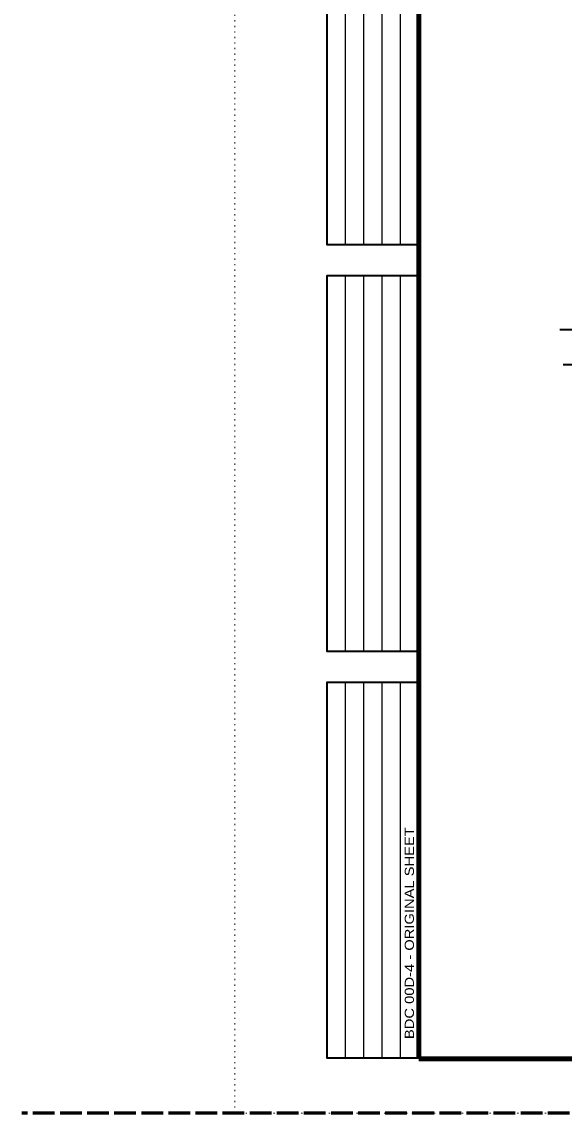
# Model space of a CAD drawing. Extents: x 312583 to 312854, y 144419 to 144597.
# Drawn here: x 312583.5 to 312628.6, y 144418.6 to 144509.2 of the extents above; entities that cross this region are included whole.
import ezdxf

# ---------------------------------------------------------------- set-up
doc = ezdxf.new("R2010")
doc.units = 0
doc.header["$LTSCALE"] = 0.3
doc.linetypes.add('DOTTED', pattern=[1.5, 0.3, -1.2])
doc.linetypes.add('LONG_DASHED', pattern=[7.5, 6, -1.5])
for name, color, linetype, lineweight in [('1', 7, 'Continuous', 40), ('2', 7, 'Continuous', 13), ('63', 7, 'DOTTED', 13)]:
    doc.layers.add(name, color=color, linetype=linetype, lineweight=lineweight)

msp = doc.modelspace()

# ---------------------------------------------------------------- linework, layer by layer
at = {"layer": '1', "linetype": 'DOTTED', "lineweight": 13}
msp.add_line((312601.2, 144418.5846), (312601.2, 144596.7846), dxfattribs=at)
at = {"layer": '1', "lineweight": 25}
for p, q in [((312610.4087, 144490.6573), (312610.4087, 144521.8756)), ((312611.9315, 144490.6573), (312611.9315, 144521.8756)), ((312613.4543, 144490.6573), (312613.4543, 144521.8756)), ((312614.9772, 144490.6573), (312614.9772, 144521.8756)), ((312610.4087, 144456.901), (312610.4087, 144488.1192)), ((312611.9315, 144456.901), (312611.9315, 144488.1192)), ((312613.4543, 144456.901), (312613.4543, 144488.1192)), ((312614.9772, 144456.901), (312614.9772, 144488.1192)), ((312610.4087, 144423.1446), (312610.4087, 144454.3629)), ((312611.9315, 144423.1446), (312611.9315, 144454.3629)), ((312613.4543, 144423.1446), (312613.4543, 144454.3629)), ((312614.9772, 144423.1446), (312614.9772, 144454.3629))]:
    msp.add_line(p, q, dxfattribs=at)
at = {"layer": '1', "lineweight": 158}
msp.add_line((312616.5, 144423.0846), (312849, 144423.0846), dxfattribs=at)
at = {"layer": '1', "linetype": 'LONG_DASHED', "lineweight": 60}
msp.add_line((312851.75, 144418.5846), (312583.526, 144418.5846), dxfattribs=at)
at = {"layer": '1', "lineweight": 158}
msp.add_lwpolyline([(312616.5, 144423.1446), (312616.5, 144585.0846), (312849, 144585.0846)], dxfattribs=at)
at = {"layer": '1', "lineweight": 35}
for points in [[(312616.5, 144490.6573), (312608.8858, 144490.6573), (312608.8858, 144521.8756), (312616.5, 144521.8756)], [(312616.5, 144456.901), (312608.8858, 144456.901), (312608.8858, 144488.1192), (312616.5, 144488.1192)], [(312616.5, 144423.1446), (312608.8858, 144423.1446), (312608.8858, 144454.3629), (312616.5, 144454.3629)]]:
    msp.add_lwpolyline(points, dxfattribs=at)
at = {"layer": '2', "lineweight": 40}
for p, q in [((312628.1899, 144483.6301), (312659.5842, 144483.6301)), ((312628.4734, 144480.7223), (312658.5921, 144480.7223))]:
    msp.add_line(p, q, dxfattribs=at)
at = {"layer": '63'}
msp.add_lwpolyline([(312601.2, 144418.5846), (312853.5, 144418.5846), (312853.5, 144596.7846)], dxfattribs=at)

# ---------------------------------------------------------------- texts
at = {"layer": '1', "width": 1.2}
msp.add_text('BDC 00D-4 - ORIGINAL SHEET', height=0.7614, rotation=90, dxfattribs=at).set_placement((312616.0832, 144424.7374))

doc.saveas('drawing.dxf')
